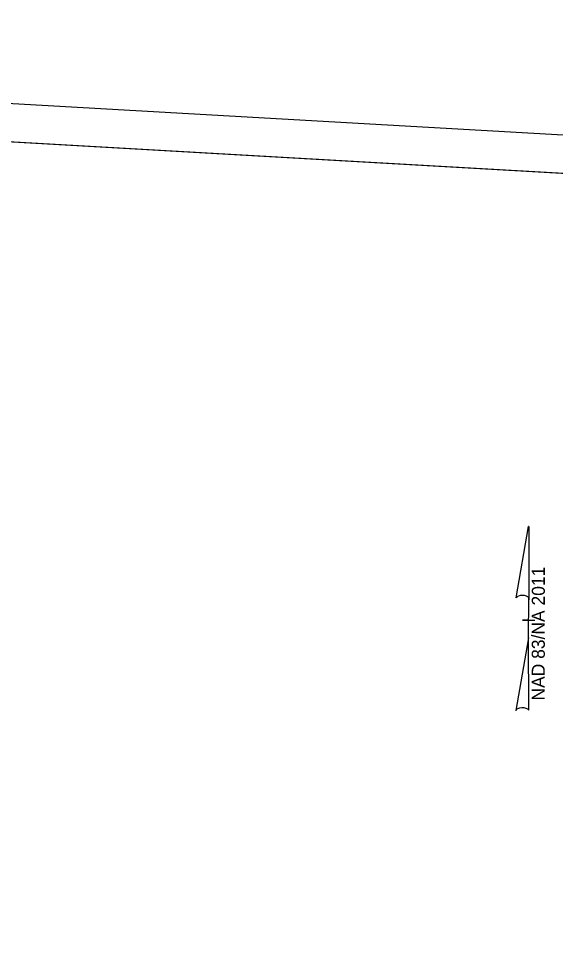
# Model space of a CAD drawing. Extents: x 2604316 to 2606605, y 617090 to 619543.
# Drawn here: x 2605358 to 2605708, y 618510 to 619107 of the extents above; entities that cross this region are included whole.
import ezdxf

# ---------------------------------------------------------------- set-up
doc = ezdxf.new("R2010")
doc.units = 0
for name, color, linetype in [('Prop North Arrow NAD83 for Plan Sheets CELL', 7, 'Continuous'), ('Scratch_Level_1', 7, 'Continuous'), ('Sheet Plan And Profile CELL', 7, 'Continuous'), ('Stewart Plot Border Xerox6279 and LJ5000', 7, 'Continuous')]:
    doc.layers.add(name, color=color, linetype=linetype)

msp = doc.modelspace()

# ---------------------------------------------------------------- linework, layer by layer
at = {"layer": 'Prop North Arrow NAD83 for Plan Sheets CELL'}
for p, q in [((2605682.58, 618730.07), (2605690.81, 618776.41)), ((2605690.86, 618776.41), (2605690.81, 618776.41)), ((2605690.86, 618776.41), (2605690.81, 618776.41)), ((2605690.86, 618776.41), (2605690.83, 618728.61)), ((2605690.81, 618703.81), (2605690.83, 618730.01)), ((2605690.83, 618728.61), (2605690.83, 618729.96)), ((2605686.82, 618715.41), (2605686.77, 618715.41)), ((2605690.37, 618715.41), (2605686.82, 618715.41)), ((2605686.87, 618715.41), (2605694.87, 618715.41)), ((2605690.81, 618703.81), (2605682.43, 618656.57)), ((2605690.83, 618656.76), (2605690.81, 618703.81))]:
    msp.add_line(p, q, dxfattribs=at)
for centre, start_param, end_param in [((2605686.72, 618729.57), 0.216388, 2.908219), ((2605686.67, 618656.4), 0.201328, 3.141593)]:
    msp.add_ellipse(centre, major_axis=(4.23, -0.03), ratio=0.461098, start_param=start_param, end_param=end_param, dxfattribs=at)
at = {"layer": 'Scratch_Level_1'}
msp.add_lwpolyline([(2606037.66, 618786.46), (2605837.94, 618797.83), (2605849.36, 618998.56), (2604589.3, 619070.32), (2604537.44, 618159.71), (2605997.22, 618076.57)], close=True, dxfattribs=at)
msp.add_lwpolyline([(2606037.66, 618786.46), (2605837.94, 618797.83), (2605849.36, 618998.56), (2604589.3, 619070.32), (2604537.44, 618159.71), (2605997.22, 618076.57)], close=True, dxfattribs=at)
at = {"layer": 'Sheet Plan And Profile CELL'}
msp.add_lwpolyline([(2606049.09, 618987.18), (2604551.51, 619072.48), (2604491.81, 618024.18), (2605989.38, 617938.88)], close=True, dxfattribs=at)
at = {"layer": 'Stewart Plot Border Xerox6279 and LJ5000'}
msp.add_lwpolyline([(2604315.67, 618009.17), (2606012.92, 617912.5), (2606075.47, 619010.72), (2604378.22, 619107.39)], close=True, dxfattribs=at)

# ---------------------------------------------------------------- texts
at = {"layer": 'Prop North Arrow NAD83 for Plan Sheets CELL'}
msp.add_text('NAD 83/NA 2011', height=8.5, rotation=89.96355, dxfattribs=at).set_placement((2605701.31, 618663.06))

doc.saveas('drawing.dxf')
